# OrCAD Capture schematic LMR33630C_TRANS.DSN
size E
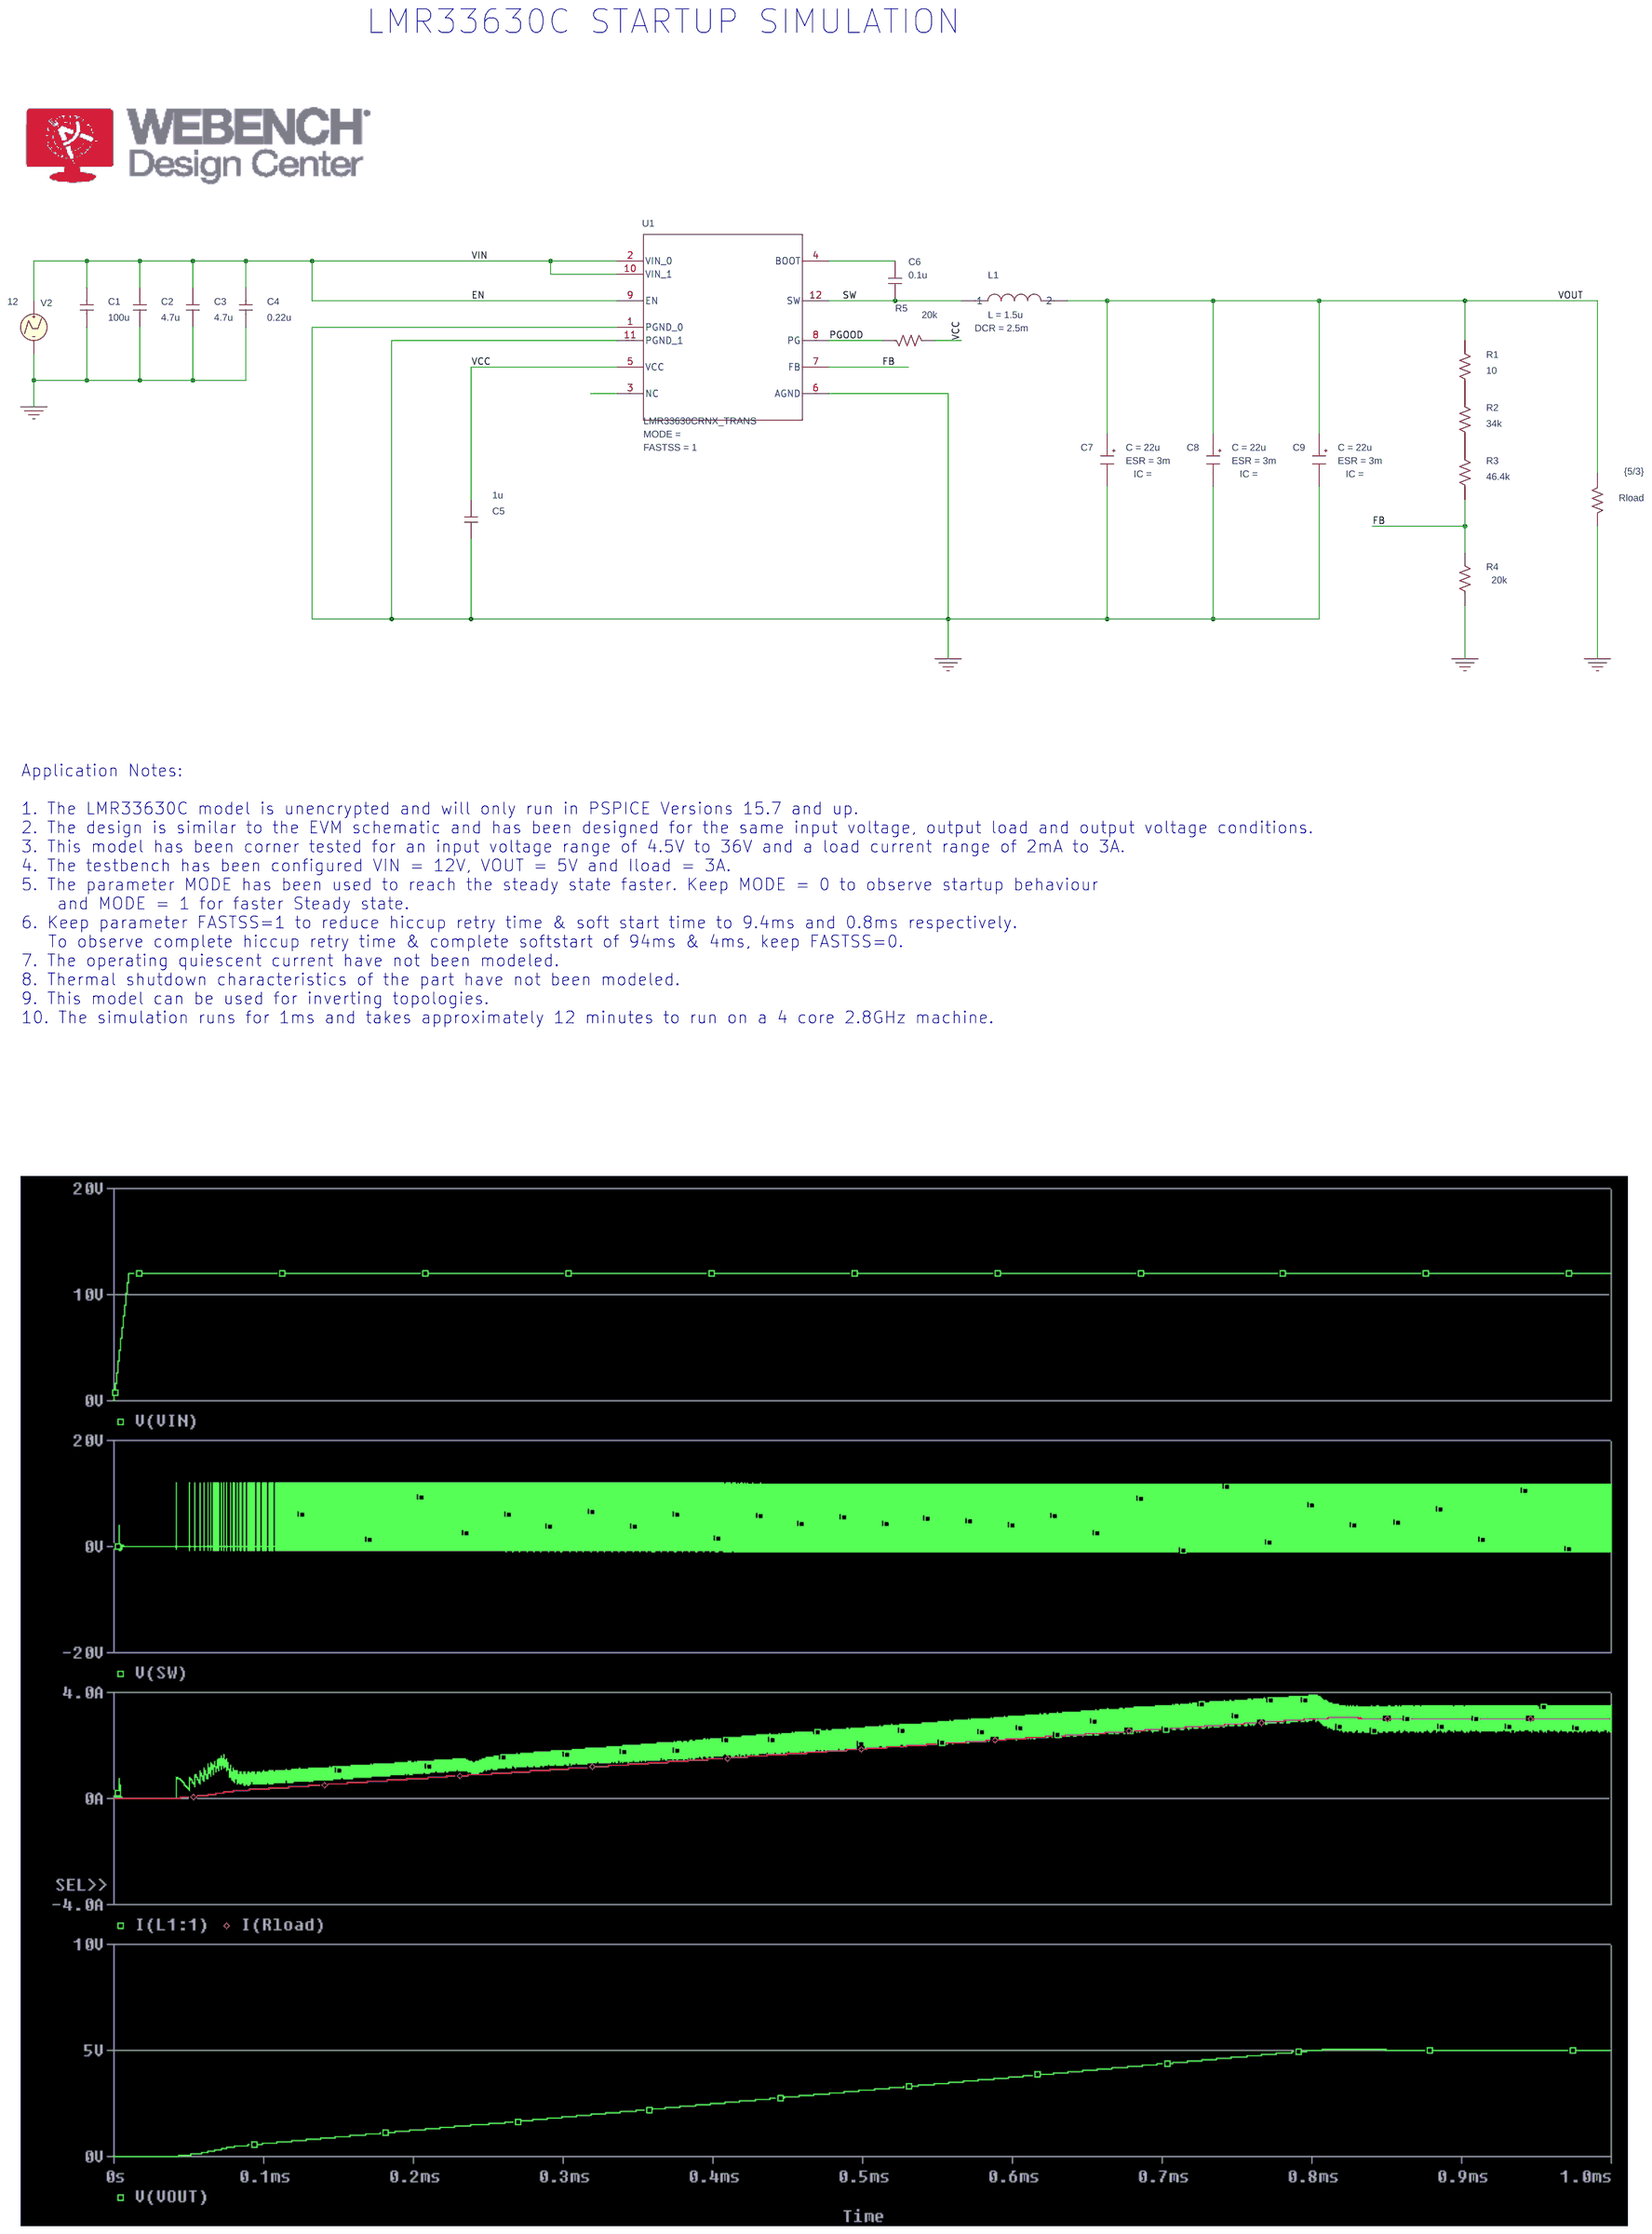
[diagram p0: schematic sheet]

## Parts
C1  100u  [RAD/CK05]
C2  4.7u  [RAD/CK05]
C3  4.7u  [RAD/CK05]
C4  0.22u  [RAD/CK05]
C5  1u  [RAD/CK05]
C6  0.1u  [RAD/CK05]
C7  CESR
C8  CESR
C9  CESR
L1  LDCR
R1  10  [AX/RC05]
R2  34k  [AX/RC05]
R3  46.4k  [AX/RC05]
R4  20k  [AX/RC05]
R5  20k  [AX/RC05]
Rload  {5/3}  [AX/RC05]
U1  LMR33630CRNX_TRANS  [RNX0012A]
V2  VPWL

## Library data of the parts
C1-C6 = C
C7-C9 = CESR_0: C: 22u; ESR: 3m; PSpiceTemplate: X^@REFDES %IN %OUT @MODEL PARAMS:  ?C|C=@C||C=100u|  ?ESR|ESR=@ESR||ESR=0.01| ?X|X=@X||X=2|  ?IC|IC=@IC||IC=2|; X: 1
L1 = LDCR: DCR: 2.5m; L: 1.5u
R1-R5 Rload = R
U1 = LMR33630CRNX_TRANS: FASTSS: 1
V2 = VPWL: PSpiceTemplate: V^@REFDES %+ %- ?DC|DC @DC| ?AC|AC @AC|\n+PWL @T1 @V1 @T2 @V2 #T3/@T3 @V3/ #T4/@T4 @V4/ #T5/@T5 @V5/ #T6/@T6 @V6/ #T7/@T7 @V7/ #T8/@T8 @V8/ #T9/@T9 @V9/ #T10/@T10 @V10/; T1: 0; T2: 10u; T3: 15m; V1: 0; V2: 12; V3: 12

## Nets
VCC: C5.1 R5.2 U1.5(VCC)
0: C1.1 C2.1 C3.1 C4.1 C5.2 C7.2(OUT) C8.2(OUT) C9.2(OUT) R4.1 Rload.2 U1.1(PGND_0) U1.6(AGND) U1.11(PGND_1) V2.2(-)
EN: C1.2 C2.2 C3.2 C4.2 U1.2(VIN_0) U1.9(EN) U1.10(VIN_1) V2.1(+)
FB: R3.1 R4.2 U1.7(FB)
PGOOD: R5.1 U1.8(PG)
SW: C6.1 L1.1 U1.12(SW)
VOUT: C7.1(IN) C8.1(IN) C9.1(IN) L1.2 R1.2 Rload.1
N17645: C6.2 U1.4(BOOT)
N16773203: R2.1 R3.2
N16773204: R1.1 R2.2

Not connected (* = marked no-connect by the designer): U1 3(NC)

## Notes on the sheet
- LMR33630C STARTUP SIMULATION
- Application Notes:
  1. The LMR33630C model is unencrypted and will only run in PSPICE Versions 15.7 and up.
  2. The design is similar to the EVM schematic and has been designed for the same input voltage, output load and output voltage conditions.
  3. This model has been corner tested for an input voltage range of 4.5V to 36V and a load current range of 2mA to 3A.
  4. The testbench has been configured VIN = 12V, VOUT = 5V and Iload = 3A.
  5. The parameter MODE has been used to reach the steady state faster. Keep MODE = 0 to observe startup behaviour
      and MODE = 1 for faster Steady state.
  6. Keep parameter FASTSS=1 to reduce hiccup retry time & soft start time to 9.4ms and 0.8ms respectively.
     To observe complete hiccup retry time & complete softstart of 94ms & 4ms, keep FASTSS=0.
  7. The operating quiescent current have not been modeled.
  8. Thermal shutdown characteristics of the part have not been modeled.
  9. This model can be used for inverting topologies.
  10. The simulation runs for 1ms and takes approximately 12 minutes to run on a 4 core 2.8GHz machine.
